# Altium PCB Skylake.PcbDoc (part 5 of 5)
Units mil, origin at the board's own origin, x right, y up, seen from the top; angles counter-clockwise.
Board outline 4000 x 4000 mil, 8 copper layers (TOP LAYER, GND1#2, SIG1#3, SIG2#4, GND2#5, SIG3#6, GND3#7, BOTTOM LAYER), stack 132.6 mil thick; 343 components, 142 nets, 972 pads, 752 vias.
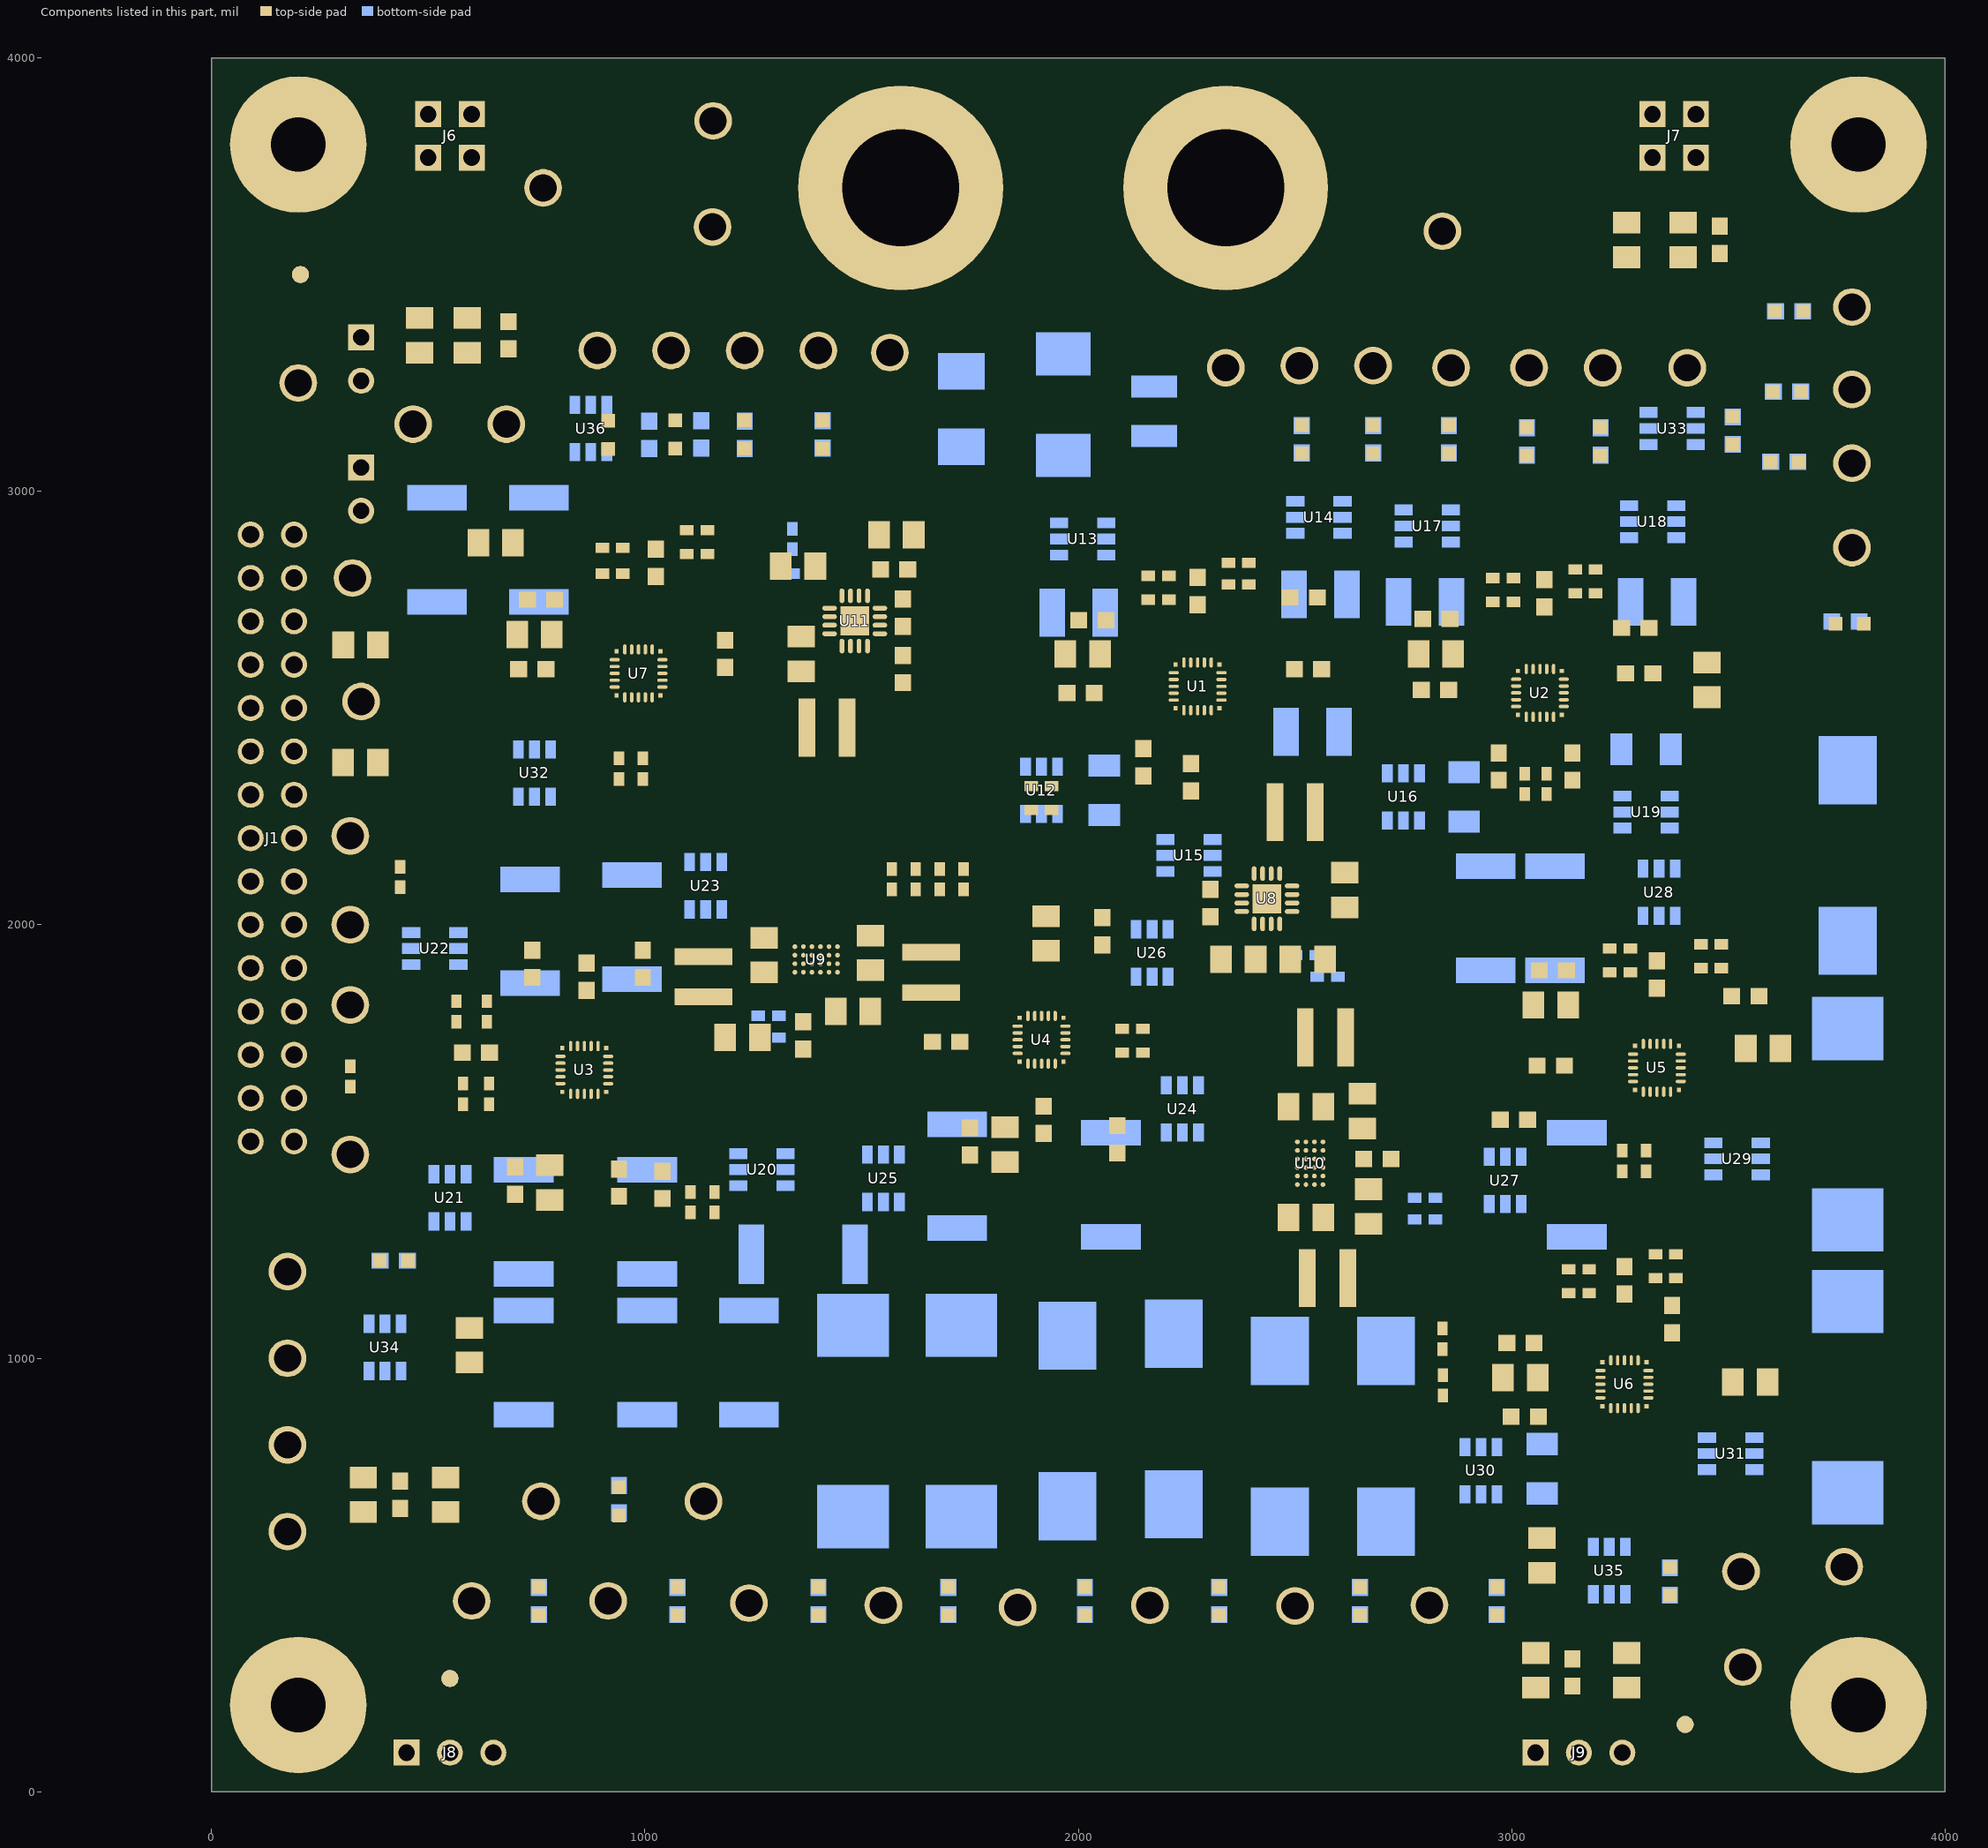
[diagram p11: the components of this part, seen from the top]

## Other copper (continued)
SIG1#3:
  pour cut-out: 1327,2559 1393,2559 1393,2522.38 1353.39,2522.38 1353.39,2522.32 1327,2522.32
  pour cut-out: 2637,1416 2703,1416 2703,1284 2637,1284
  pour cut-out: 2622,1636 2688,1636 2688,1504 2622,1504
  pour cut-out: 1159,1707 1159,1773 1291,1773 1291,1707
  pour cut-out: 1414,1767 1414,1833 1546,1833 1546,1767
  pour cut-out: 2582,2146 2648,2146 2648,2014 2582,2014
  pour cut-out: 1327,2691 1393,2691 1393,2559 1327,2559
  pour cut-out: 2566.22,2192.59 2526.14,2192.59 2526.14,2327.77 2566.22,2327.77 2566.22,2192.56
  pour cut-out: 2636.22,1672.11 2596.16,1672.11 2596.16,1807.29 2636.24,1807.29 2636.24,1672.08
  pour cut-out: 2641.09,1117.1 2601.01,1117.1 2601.01,1252.28 2641.09,1252.28 2641.09,1117.07
  pour cut-out: 1592.42,1823.22 1592.42,1863.28 1727.6,1863.28 1727.6,1823.2 1592.39,1823.2
  pour cut-out: 1067.57,1813.05 1067.57,1853.11 1202.75,1853.11 1202.75,1813.03 1067.54,1813.03
  pour cut-out: 1337.71,1925.55 1337.71,1937.71 1392.31,1937.71 1392.31,1921.82 1337.67,1921.82 1337.67,1925.52
  pour cut-out: 1397.43,1925.53 1397.43,1937.69 1451.84,1937.69 1451.84,1921.8 1397.39,1921.8 1397.39,1925.5
  pour cut-out: 2520.69,1506.47 2532.85,1506.47 2532.85,1454.35 2516.96,1454.35 2516.96,1506.51 2520.66,1506.51
  pour cut-out: 1067.1,1906.59 1067.1,1946.66 1202.28,1946.66 1202.28,1906.57 1067.07,1906.57
  pour cut-out: 1591.95,1916.26 1591.95,1956.33 1727.14,1956.33 1727.14,1916.25 1591.93,1916.25
  pour cut-out: 2520.69,1447.41 2532.85,1447.41 2532.85,1395.29 2516.96,1395.29 2516.96,1447.45 2520.66,1447.45
  pour cut-out: 2508.03,1252.14 2548.1,1252.14 2548.1,1116.97 2508.02,1116.97 2508.02,1252.18
  pour cut-out: 2503.24,1807.44 2543.31,1807.44 2543.31,1672.26 2503.23,1672.26 2503.23,1807.47
  pour cut-out: 2425.18,2133.53 2470.5,2133.53 2470.5,2101.29 2419.57,2101.29 2419.57,2133.42 2425.18,2133.42
  pour cut-out: 2433.41,2327.8 2473.49,2327.8 2473.49,2192.62 2433.41,2192.62 2433.41,2327.83
  pour cut-out: 1472.71,2657.64 1498.66,2657.64 1498.66,2633.94 1469.22,2633.94 1469.22,2657.71 1472.75,2657.71
  pour cut-out: 1353.32,2522.76 1393.39,2522.76 1393.39,2387.58 1353.31,2387.58 1353.31,2522.79
  pour cut-out: 1446.23,2522.57 1486.3,2522.57 1486.3,2387.39 1446.22,2387.39 1446.22,2522.6
  pour cut-out: 2840,3545 cw(c2840,3600) 2785,3600 cw(c2840,3600) 2840,3655 cw(c2840,3600) 2895,3600 cw(c2840,3600)
  text ".Layer_Name" at 591.64,-858.77 h60
SIG2#4:
  pour cut-out: 1327,2559 1393,2559 1393,2522.38 1353.39,2522.38 1353.39,2522.32 1327,2522.32
  pour cut-out: 2637,1416 2703,1416 2703,1284 2637,1284
  pour cut-out: 2622,1636 2688,1636 2688,1504 2622,1504
  pour cut-out: 2582,2146 2648,2146 2648,2014 2582,2014
  pour cut-out: 1159,1707 1159,1773 1291,1773 1291,1707
  pour cut-out: 1414,1767 1414,1833 1546,1833 1546,1767
  pour cut-out: 1327,2691 1393,2691 1393,2559 1327,2559
  pour cut-out: 1393.33,2387.42 1353.26,2387.42 1353.26,2522.6 1393.34,2522.6 1393.34,2387.39
  pour cut-out: 2566.33,2192.42 2526.26,2192.42 2526.26,2327.6 2566.34,2327.6 2566.34,2192.39
  pour cut-out: 2641.33,1117.42 2601.26,1117.42 2601.26,1252.6 2641.34,1252.6 2641.34,1117.39
  pour cut-out: 2636.33,1672.42 2596.26,1672.42 2596.26,1807.6 2636.34,1807.6 2636.34,1672.39
  pour cut-out: 1592.42,1823.67 1592.42,1863.74 1727.6,1863.74 1727.6,1823.66 1592.39,1823.66
  pour cut-out: 1067.42,1813.66 1067.42,1853.74 1202.6,1853.74 1202.6,1813.66 1067.39,1813.66
  pour cut-out: 1392.48,1934.02 1392.48,1921.86 1338.06,1921.86 1338.06,1937.75 1392.52,1937.75 1392.52,1934.05
  pour cut-out: 1451.82,1934.07 1451.82,1921.91 1397.4,1921.91 1397.4,1937.8 1451.86,1937.8 1451.86,1934.1
  pour cut-out: 2528.99,1392.34 2516.83,1392.34 2516.83,1446.76 2532.72,1446.76 2532.72,1392.3 2529.02,1392.3
  pour cut-out: 2529.27,1452.38 2517.11,1452.38 2517.11,1506.8 2533,1506.8 2533,1452.34 2529.3,1452.34
  pour cut-out: 1067.42,1906.66 1067.42,1946.74 1202.6,1946.74 1202.6,1906.66 1067.39,1906.66
  pour cut-out: 1592.44,1916.6 1592.44,1956.67 1727.62,1956.67 1727.62,1916.59 1592.41,1916.59
  pour cut-out: 2508.31,1253.26 2548.38,1253.26 2548.38,1118.07 2508.3,1118.07 2508.3,1253.28
  pour cut-out: 2503.41,1807.58 2543.47,1807.58 2543.47,1672.4 2503.39,1672.4 2503.39,1807.61
  pour cut-out: 2406.01,2117.53 2405.47,2118.07 2405.47,2330.3 2415.08,2339.91 2472.69,2339.91 2486.36,2326.24 2486.36,2107.36 2476.25,2097.25 2418.1,2097.25 2406.01,2109.34
  pour cut-out: 1456.7,2652.79 1456.7,2609.13 1429.59,2582.02 1429.59,2388.54 1443.84,2374.29 1444.76,2375.21 1491.17,2375.21 1503.58,2387.62 1503.58,2654.64 1496.88,2661.34 1464.98,2661.34 1457,2653.36
  text ".Layer_Name" at 595.57,-859.7 h60
GND2#5:
  pour cut-out: 1327,2559 1393,2559 1393,2522.38 1353.39,2522.38 1353.39,2522.32 1327,2522.32
  pour cut-out: 941,2718 850,2627 850,2529 939,2440 1129,2440 1188,2499 1188,2553 1209,2574 1209,3012 1187,3034 1187,3127 1219,3159 1750,3159 1766,3175 1954,3175 2245,2884 2329,2884 2404,2809 2404,2700 2368,2664 2269,2664 2256,2677 2248,2669 2265,2652 2376,2652 2417,2693 2417,2815 2334,2898 2250,2898 1960,3188 1758,3188 1743,3173 1209,3173 1173,3137 1173,3029 1197,3005 1197,2582 1175,2560 1175,2505 1123,2453 943,2453 860,2536 860,2620 944,2704 945,2704 945,2718
  pour cut-out: 3082.93,2682.21 3076.13,2689 2983,2689 2961,2667 2895,2667 2876,2648 2876,2462 2906,2432 2960,2432 3078,2314 3078,2171 3360,1889 3397,1889 3428,1858 3428,1811 3412.12,1795.12 3376.77,1795.12 3376.77,1804.88 3376.9,1805 3407,1805 3418,1816 3418,1852 3392,1878 3355,1878 3067,2166 3067,2310 2955,2422 2900,2422 2865,2457 2865,2652 2891,2678 2957,2678 2978,2699 3079.93,2699 3089.82,2689.1
  pour cut-out: 991,2726 940,2726 844,2630 844,2526 967,2403 1156,2403 1202,2449 1202,2547 1245,2590 1245,2701 1217,2729 1217,3018 1196,3039 1196,3110 1233,3147 1754,3147 1776,3169 1950,3169 2245,2874 2319,2874 2366,2827 2366,2701 2339,2674 2315,2674 2315,2685 2335,2685 2355,2705 2355,2822 2314,2863 2241,2863 1947,3157 1779,3157 1759,3137 1240,3137 1208,3105 1208,3043 1226,3025 1226,2734 1254,2706 1254,2586 1211,2543 1211,2444 1160,2393 964,2393 835,2522 835,2635 936,2736 996,2736 1012,2720 1005,2713 1004,2713
  pour cut-out: 1159,1707 1159,1773 1291,1773 1291,1707
  pour cut-out: 1414,1767 1414,1833 1546,1833 1546,1767
  pour cut-out: 2637,1416 2703,1416 2703,1284 2637,1284
  pour cut-out: 2622,1636 2688,1636 2688,1504 2622,1504
  pour cut-out: 2582,2146 2648,2146 2648,2014 2582,2014
  pour cut-out: 1327,2691 1393,2691 1393,2559 1327,2559
  pour cut-out: 1392.93,2387.35 1352.86,2387.35 1352.86,2522.53 1392.94,2522.53 1392.94,2387.32
  pour cut-out: 2640.93,1117.35 2600.86,1117.35 2600.86,1252.53 2640.94,1252.53 2640.94,1117.32
  pour cut-out: 2635.93,1672.35 2595.86,1672.35 2595.86,1807.53 2635.94,1807.53 2635.94,1672.32
  pour cut-out: 2565.93,2192.35 2525.86,2192.35 2525.86,2327.53 2565.94,2327.53 2565.94,2192.32
  pour cut-out: 1592.35,1824.07 1592.35,1864.14 1727.53,1864.14 1727.53,1824.06 1592.32,1824.06
  pour cut-out: 1067.35,1814.07 1067.35,1854.14 1202.53,1854.14 1202.53,1814.06 1067.32,1814.06
  pour cut-out: 1392.48,1933.86 1392.48,1921.7 1338.07,1921.7 1338.07,1937.59 1392.52,1937.59 1392.52,1933.89
  pour cut-out: 1451.69,1934.26 1451.69,1922.1 1397.28,1922.1 1397.28,1937.99 1451.73,1937.99 1451.73,1934.29
  pour cut-out: 2529.28,1393.12 2517.12,1393.12 2517.12,1447.53 2533.01,1447.53 2533.01,1393.08 2529.31,1393.08
  pour cut-out: 2529.22,1452.34 2517.06,1452.34 2517.06,1506.75 2532.95,1506.75 2532.95,1452.3 2529.25,1452.3
  pour cut-out: 1592.38,1916.61 1592.38,1956.68 1727.56,1956.68 1727.56,1916.59 1592.35,1916.59
  pour cut-out: 1067.35,1907.07 1067.35,1947.14 1202.53,1947.14 1202.53,1907.06 1067.32,1907.06
  pour cut-out: 2508.38,1252.82 2548.45,1252.82 2548.45,1117.64 2508.37,1117.64 2508.37,1252.86
  pour cut-out: 2503.28,1807.55 2543.35,1807.55 2543.35,1672.36 2503.27,1672.36 2503.27,1807.57
  pour cut-out: 2407.76,2119.98 2407.22,2120.53 2407.22,2332.75 2416.83,2342.36 2474.44,2342.36 2488.11,2328.69 2488.11,2109.81 2478,2099.7 2419.85,2099.7 2407.76,2111.79
  pour cut-out: 1457.04,2652.76 1457.04,2609.1 1429.93,2581.99 1429.93,2388.51 1444.18,2374.26 1445.1,2375.18 1491.51,2375.18 1503.92,2387.59 1503.92,2654.61 1497.22,2661.31 1465.32,2661.31 1457.34,2653.33
  pour cut-out: 3365,1787.5 cw(c3365,1800) 3352.5,1800 cw(c3365,1800) 3365,1812.5 cw(c3365,1800) 3377.5,1800 cw(c3365,1800)
  pour cut-out: 3094.7,2664.83 cw(c3094.7,2677.33) 3082.2,2677.33 cw(c3094.7,2677.33) 3094.7,2689.83 cw(c3094.7,2677.33) 3107.2,2677.33 cw(c3094.7,2677.33)
  pour cut-out: 2305,2667.5 cw(c2305,2680) 2292.5,2680 cw(c2305,2680) 2305,2692.5 cw(c2305,2680) 2317.5,2680 cw(c2305,2680)
  pour cut-out: 1015,2697.5 cw(c1015,2710) 1002.5,2710 cw(c1015,2710) 1015,2722.5 cw(c1015,2710) 1027.5,2710 cw(c1015,2710)
  pour cut-out: 1015,2700 cw(c1015,2710) 1005,2710 cw(c1015,2710) 1015,2720 cw(c1015,2710) 1025,2710 cw(c1015,2710)
  pour cut-out: 1015,2700 cw(c1015,2710) 1005,2710 cw(c1015,2710) 1015,2720 cw(c1015,2710) 1025,2710 cw(c1015,2710)
  pour cut-out: 1015,2700 cw(c1015,2710) 1005,2710 cw(c1015,2710) 1015,2720 cw(c1015,2710) 1025,2710 cw(c1015,2710)
  text ".Layer_Name" at 586.85,-860.23 h60
SIG3#6:
  pour cut-out: 1327.69,2558.33 1393.69,2558.33 1393.69,2521.71 1354.08,2521.71 1354.08,2521.65 1327.69,2521.65
  pour cut-out: 1159,1707 1159,1773 1291,1773 1291,1707
  pour cut-out: 1414,1767 1414,1833 1546,1833 1546,1767
  pour cut-out: 2637,1416 2703,1416 2703,1284 2637,1284
  pour cut-out: 2622,1636 2688,1636 2688,1504 2622,1504
  pour cut-out: 2582,2146 2648,2146 2648,2014 2582,2014
  pour cut-out: 1327,2691 1393,2691 1393,2559 1327,2559
  pour cut-out: 1392.93,2387.47 1352.86,2387.47 1352.86,2522.65 1392.94,2522.65 1392.94,2387.44
  pour cut-out: 2640.93,1117.47 2600.86,1117.47 2600.86,1252.65 2640.94,1252.65 2640.94,1117.44
  pour cut-out: 2635.93,1672.47 2595.86,1672.47 2595.86,1807.65 2635.94,1807.65 2635.94,1672.44
  pour cut-out: 2565.93,2192.47 2525.86,2192.47 2525.86,2327.65 2565.94,2327.65 2565.94,2192.44
  pour cut-out: 1592.47,1824.07 1592.47,1864.14 1727.65,1864.14 1727.65,1824.06 1592.44,1824.06
  pour cut-out: 1067.47,1814.07 1067.47,1854.14 1202.65,1854.14 1202.65,1814.05 1067.44,1814.05
  pour cut-out: 1392.71,1934.26 1392.71,1922.1 1338.3,1922.1 1338.3,1937.99 1392.75,1937.99 1392.75,1934.29
  pour cut-out: 1451.76,1934.21 1451.76,1922.05 1397.35,1922.05 1397.35,1937.94 1451.8,1937.94 1451.8,1934.24
  pour cut-out: 2529.11,1393.1 2516.95,1393.1 2516.95,1447.51 2532.84,1447.51 2532.84,1393.06 2529.14,1393.06
  pour cut-out: 2529.2,1452.24 2517.04,1452.24 2517.04,1506.65 2532.93,1506.65 2532.93,1452.2 2529.23,1452.2
  pour cut-out: 1067.47,1907.07 1067.47,1947.14 1202.65,1947.14 1202.65,1907.05 1067.44,1907.05
  pour cut-out: 1592.19,1916.52 1592.19,1956.59 1727.37,1956.59 1727.37,1916.51 1592.16,1916.51
  pour cut-out: 2508.28,1252.69 2548.34,1252.69 2548.34,1117.51 2508.26,1117.51 2508.26,1252.72
  pour cut-out: 2503.14,1807.13 2543.21,1807.13 2543.21,1671.95 2503.13,1671.95 2503.13,1807.16
  pour cut-out: 2405.93,2118.28 2405.39,2118.82 2405.39,2331.05 2415,2340.66 2472.61,2340.66 2486.28,2326.99 2486.28,2108.11 2476.17,2098 2418.02,2098 2405.93,2110.09
  pour cut-out: 1457.81,2652.43 1457.81,2608.77 1430.7,2581.66 1430.7,2388.18 1444.95,2373.93 1445.87,2374.85 1492.28,2374.85 1504.69,2387.26 1504.69,2654.28 1497.99,2660.98 1466.09,2660.98 1458.11,2653
  text ".Layer_Name" at 585.44,-857.07 h60
GND3#7:
  pour cut-out: 1327,2559 1393,2559 1393,2522.38 1353.39,2522.38 1353.39,2522.32 1327,2522.32
  pour cut-out: 2258,2682 2247,2693 2267,2713 2267,2899 2223,2943 2223,3311 2299,3387 2909,3387 2980,3316 2980,3041 3148,2873 3148,2669 3123,2644 3048,2644 3038,2654 3015,2654 3005,2644 3005,2615 3016,2604 3016,2541 2971,2496 2971,2402 3036,2337 3216,2337 3259,2294 3259,1879 3319,1819 3319,1792 3311,1784 3300,1784 3291,1793 3232,1793 3163,1724 3163,1395 3192,1366 3192,1117 3227,1082 3218,1073 3178,1113 3178,1360 3149,1389 3149,1732 3223,1806 3293,1806 3298,1811 3298,1817 3246,1869 3246,2286 3209,2323 3028,2323 2957,2394 2957,2503 3002,2548 3002,2597 2992,2607 2992,2655 3014,2677 3038,2677 3058,2657 3115,2657 3135,2677 3135,2868 2963,3040 2963,3312 2904,3371 2308,3371 2238,3301 2238,2947 2280,2905 2280,2704
  pour cut-out: 364,1824 508,1824 613,1719 657,1719 726,1650 736,1650 765,1679 765,1756 821,1812 976,1812 1251,1537 1592,1537 1768,1713 1775,1713 1775,1694 1598,1517 1252,1517 970,1799 828,1799 778,1749 778,1662 739,1623 725,1623 715,1633 715,1639 650,1704 609,1704 507,1806 364,1806
  pour cut-out: 81,1969 98,1969 98,1928 138,1888 256,1888 293,1851 282,1840 250,1872 131,1872 81,1922
  pour cut-out: 114.5,2035.5 125,2025 143,2043 244,2043 276,2075 737,2075 912,2250 912,2323 999,2410 999,2533 990,2542 990,2683 966,2707 957,2698 977,2678 977,2535 985,2527 985,2418 897,2330 897,2258 730,2091 268,2091 235,2058 137,2058
  pour cut-out: 3278,1072 3255,1095 3255,1323 3174,1404 3174,1720 3213,1759 3314,1759 3353,1798 3363,1788 3321,1746 3218,1746 3186,1714 3186,1409 3267,1328 3267,1101 3287,1081
  pour cut-out: 2307,2692 2338,2723 2338,2892 2250,2980 2250,3303 2308,3361 2902,3361 2956,3307 2956,3026 3080,2902 3080,2701 3092,2689 3083,2680 3066,2697 3066,2894 2939,3021 2939,3298 2892,3345 2317,3345 2265,3293 2265,2985 2350,2900 2350,2715 2317,2682
  pour cut-out: 346,2038 363,2055 902,2055 1007,2160 1007,2479 1032,2504 1031,2505 1031,2601 998,2634 998,2703 1002,2707 1011,2698 1011,2639 1046,2604 1046,2495 1023,2472 1023,2154 909,2040 374,2040 359,2025
  pour cut-out: 220,2008 276,2008 276,1993 220,1993
  pour cut-out: 727,1705 735,1705 735,1747 814,1826 977,1826 1188,1615 1381,1615 1406,1640 1636,1640 1727,1731 1760,1731 1782,1753 1773,1762 1754,1743 1720,1743 1630,1653 1396,1653 1374,1631 1199,1631 991,1839 811,1839 725,1753 725,1707
  pour cut-out: 312,1957 312,1924 384,1852 562,1852 718,1696 727,1705 567,1865 392,1865 327,1930 327,1957
  pour cut-out: 1159,1707 1159,1773 1291,1773 1291,1707
  pour cut-out: 1414,1767 1414,1833 1546,1833 1546,1767
  pour cut-out: 2637,1416 2703,1416 2703,1284 2637,1284
  pour cut-out: 2622,1636 2688,1636 2688,1504 2622,1504
  pour cut-out: 2582,2146 2648,2146 2648,2014 2582,2014
  pour cut-out: 1327,2691 1393,2691 1393,2559 1327,2559
  pour cut-out: 1393.7,2387.96 1353.63,2387.96 1353.63,2523.14 1393.71,2523.14 1393.71,2387.93
  pour cut-out: 2641.7,1117.96 2601.63,1117.96 2601.63,1253.14 2641.71,1253.14 2641.71,1117.93
  pour cut-out: 2636.7,1672.96 2596.63,1672.96 2596.63,1808.14 2636.71,1808.14 2636.71,1672.93
  pour cut-out: 2566.7,2192.96 2526.63,2192.96 2526.63,2328.14 2566.71,2328.14 2566.71,2192.93
  pour cut-out: 1592.96,1823.3 1592.96,1863.37 1728.14,1863.37 1728.14,1823.29 1592.93,1823.29
  pour cut-out: 1067.96,1813.3 1067.96,1853.36 1203.14,1853.36 1203.14,1813.28 1067.93,1813.28
  pour cut-out: 1392.6,1934.09 1392.6,1921.93 1338.19,1921.93 1338.19,1937.82 1392.64,1937.82 1392.64,1934.12
  pour cut-out: 1451.86,1934.22 1451.86,1922.06 1397.45,1922.06 1397.45,1937.95 1451.9,1937.95 1451.9,1934.25
  pour cut-out: 2529,1393.06 2516.84,1393.06 2516.84,1447.47 2532.73,1447.47 2532.73,1393.02 2529.03,1393.02
  pour cut-out: 2529.18,1452.2 2517.02,1452.2 2517.02,1506.61 2532.91,1506.61 2532.91,1452.16 2529.21,1452.16
  pour cut-out: 1592.24,1916.44 1592.24,1956.51 1727.41,1956.51 1727.41,1916.43 1592.2,1916.43
  pour cut-out: 1067.96,1906.3 1067.96,1946.36 1203.14,1946.36 1203.14,1906.28 1067.93,1906.28
  pour cut-out: 2508.45,1253.3 2548.53,1253.3 2548.53,1118.12 2508.45,1118.12 2508.45,1253.33
  pour cut-out: 2503.21,1808.09 2543.28,1808.09 2543.28,1672.91 2503.2,1672.91 2503.2,1808.12
  pour cut-out: 2406.33,2118.94 2405.79,2119.48 2405.79,2331.71 2415.4,2341.32 2473.01,2341.32 2486.68,2327.65 2486.68,2108.77 2476.57,2098.66 2418.42,2098.66 2406.33,2110.75
  pour cut-out: 1459.12,2652.43 1459.12,2608.77 1432.01,2581.66 1432.01,2388.18 1446.26,2373.93 1447.18,2374.85 1493.59,2374.85 1506,2387.26 1506,2654.28 1499.3,2660.98 1467.4,2660.98 1459.42,2653
  pour cut-out: 190,1960 cw(c190,2000) 150,2000 cw(c190,2000) 190,2040 cw(c190,2000) 230,2000 cw(c190,2000)
  pour cut-out: 320,1948 cw(c320,2000) 268,2000 cw(c320,2000) 320,2052 cw(c320,2000) 372,2000 cw(c320,2000)
  pour cut-out: 3365,1787.5 cw(c3365,1800) 3352.5,1800 cw(c3365,1800) 3365,1812.5 cw(c3365,1800) 3377.5,1800 cw(c3365,1800)
  pour cut-out: 3290,1057.5 cw(c3290,1070) 3277.5,1070 cw(c3290,1070) 3290,1082.5 cw(c3290,1070) 3302.5,1070 cw(c3290,1070)
  pour cut-out: 3094.7,2664.83 cw(c3094.7,2677.33) 3082.2,2677.33 cw(c3094.7,2677.33) 3094.7,2689.83 cw(c3094.7,2677.33) 3107.2,2677.33 cw(c3094.7,2677.33)
  pour cut-out: 2305,2667.5 cw(c2305,2680) 2292.5,2680 cw(c2305,2680) 2305,2692.5 cw(c2305,2680) 2317.5,2680 cw(c2305,2680)
  pour cut-out: 1785,1752.18 cw(c1785,1764.68) 1772.5,1764.68 cw(c1785,1764.68) 1785,1777.18 cw(c1785,1764.68) 1797.5,1764.68 cw(c1785,1764.68)
  pour cut-out: 1015,2697.5 cw(c1015,2710) 1002.5,2710 cw(c1015,2710) 1015,2722.5 cw(c1015,2710) 1027.5,2710 cw(c1015,2710)
  pour cut-out: 730,1682.5 cw(c730,1695) 717.5,1695 cw(c730,1695) 730,1707.5 cw(c730,1695) 742.5,1695 cw(c730,1695)
  text ".Layer_Name" at 586.85,-860.23 h60
BOTTOM LAYER:
  rectangle net GND: 2240,2515 2310,2585
  rectangle net GND: 3030,2500 3100,2570
  rectangle net GND: 2401.39,2026.35 2468.64,2093.41
  rectangle net GND: 1450.39,2667.35 1517.64,2734.41
  pour cut-out: 1216.37,2551.97 1282.37,2551.97 1282.37,2515.35 1242.76,2515.35 1242.76,2515.29 1216.37,2515.29
  region net V3.3DX_3G4G: 2070.84,1971.74 2101.6,1971.74 2109.86,1963.48 2109.86,1912.39 2119.13,1903.12 2143.39,1903.12 2145.04,1901.47 2145.04,1858.39 2139.39,1852.74 2093.24,1852.74 2064.06,1881.92 2064.06,1964.96
  region net GND: 3700,2480 3850,2480 3880,2450 3880,2285 3855,2260 3700,2260 3660.83,2299.17 3660.83,2440.83
  region net NetR85_2: 3840,2080 3875,2045 3875,1685 3855,1665 3700,1665 3670,1695 3670,2040 3710,2080
  pour cut-out: 1451.48,1934.02 1451.48,1921.86 1397.07,1921.86 1397.07,1937.75 1451.52,1937.75 1451.52,1934.05
  pour cut-out: 1392.58,1934.18 1392.58,1922.02 1338.17,1922.02 1338.17,1937.91 1392.62,1937.91 1392.62,1934.21
  pour cut-out: 2529.04,1452.29 2516.88,1452.29 2516.88,1506.7 2532.77,1506.7 2532.77,1452.25 2529.07,1452.25
  pour cut-out: 2529.17,1392.58 2517.01,1392.58 2517.01,1446.99 2532.9,1446.99 2532.9,1392.54 2529.2,1392.54
  region net V3.3DX_WIFI: 3864,841 3695,841 3695,617 3864,617
  region net GND: 2556.45,2835.07 2560.66,2839.28 2639.58,2839.28 2651.08,2827.78 2651.08,2703.66 2643.03,2695.61 2565.64,2695.61 2551.85,2709.4 2551.85,2831.62 2555.68,2835.45
  region net GND: 2680.69,2808.39 2800.38,2808.39 2811.75,2797.02 2811.75,2534.17 2777.52,2499.94 2725.75,2499.94 2672.68,2553.01 2672.68,2800.38
  region net NetR72_2: 1177.26,1315.37 1295.59,1315.37 1314.17,1296.79 1314.17,1069.26 1293.95,1049.04 1172.61,1049.04 1153.39,1068.26 1153.39,1291.5
  region net V1(1.8V): 3453.44,3125.74 3459.57,3119.61 3459.57,3074.75 3451.51,3066.69 3404.37,3066.69 3397.93,3073.13 3397.93,3121.22 3402.45,3125.74
  region net V3(3.3V): 3142.8,480.99 3195.63,480.99 3200.42,476.2 3200.42,406.22 3193.19,398.99 3142.99,398.99 3135.28,406.7 3135.28,473.47
  region net V2(3.3V): 432.45,1148.25 474.67,1148.25 481.32,1141.6 481.32,1062.38 475.97,1057.03 426.84,1057.03 424.53,1059.34 424.53,1140.33
  region net V3.3DX_USBSDIO: 938.81,1503.46 1087.54,1503.46 1103.27,1487.73 1103.27,1410.85 1090.88,1398.46 933.15,1398.46 923.12,1408.49 923.12,1487.77
  region net V3.3S: 3041.4,846.33 3122.09,846.33 3137.35,831.07 3137.35,763.95 3128.53,755.13 3041.85,755.13 3025.13,771.85 3025.13,830.06
  region net V3.3A_EC: 672.46,1913.43 804.6,1913.43 814.25,1903.78 814.25,1813.18 795.4,1794.33 676.61,1794.33 657.96,1812.98 657.96,1898.93
  region net V3.3DX_SENSORS: 921.75,1927.74 921.76,1927.75 1056.69,1927.75 1070.13,1914.31 1070.13,1852.68 1059.33,1841.88 898.97,1841.88 891.67,1849.18 891.67,1912.56 906.86,1927.75 922.34,1927.75
  region net V3.3DX_EDP: 575.42,1512 588.3,1524.88 660.49,1524.88 678.73,1506.64 678.73,1405.87 664.3,1391.44 583.63,1391.44 575.42,1399.65
  text ".Layer_Name" at 577,-858.49 h60
Multi-Layer:
  circle w8: c-264,1 r26
  circle w8: c-264,1 r13
  circle w8: c-264,1 r40
  circle w8: c4324,-2 r26
  circle w8: c4324,-2 r13
  circle w8: c4324,-2 r40
  circle w8: c4326,4009 r26
  circle w8: c4326,4009 r13
  circle w8: c4326,4009 r40
  lines w8: -320,0 -264,0 ; -264,-56 -264,0 ; -264,56 -264,0 ; -208,0 -264,0 ; 4268,-3 4324,-3 ; 4270,4008 4326,4008 ; 4324,-59 4324,-3 ; 4324,53 4324,-3 ; 4326,3952 4326,4008 ; 4326,4064 4326,4008 ; 4380,-3 4324,-3 ; 4382,4008 4326,4008

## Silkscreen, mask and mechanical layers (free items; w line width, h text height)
Top Overlay:
  drawing of 296 lines, arcs and shapes, not listed
  text "1" at 3475,3010 h30
  text "V1(1.8V)" at 3398,2995.88 h30 r90
  text "J1" at 130,2952 h30
  text "GPIO12" at 28.26,2837.09 h30
  text "GND" at 61.3,2742.6 h30
  text "NETJ1_6" at 140.4,2742.6 h30
  text "GND" at 53.22,2639.09 h30
  text "TPS22993" at 870.47,2556.79 h30 r90
  text "TPS62130" at 1421,2553 h30
  text "GND" at 58.36,2535.5 h30
  text "2" at 3790,2530 h30
  text "TPS22993" at 2136.98,2512.86 h30 r90
  text "TPS22993" at 2933.06,2436.68 h30 r90
  text "GPIO6" at 17.13,2336.86 h30
  text "GPIO7" at 147.4,2337.32 h30
  text "GPIO4" at 16.67,2236.15 h30
  text "GPIO5" at 140.93,2236.15 h30
  text "1" at 3877.76,2143.35 h30
  text "GND" at 55.6,2140.8 h30
  text "NETJ2_6" at 139.8,2138.2 h30
  text "TPS62151" at 2186.55,2122.86 h30
  text "GPIO2" at 21.32,2038.15 h30
  text "GPIO3" at 145.47,2037.86 h30
  text "TPS62182" at 1421,1995 h30 r90
  text "SDA" at 66,1941.9 h30
  text "SCL" at 167.9,1940.8 h30
  text "TPS22993" at 1860.28,1856.14 h30
  text "TPS22993" at 827.52,1781.3 h30
  text "GPIO8" at 18.6,1636.83 h30
  text "GPIO9" at 155.81,1637.35 h30
  text "TPS22993" at 3202.13,1623.85 h30 r90
  text "GND" at 52.62,1537.66 h30
  text "GND" at 151.93,1538.18 h30
  text "2" at 3875,1510 h30
  text "GPIO10" at 25,1440 h30
  text "GPIO11" at 140,1440 h30
  text "TPS62182" at 2295.61,1406.94 h30
  text "V3.3A_EC" at 330.21,1153.12 h30
  text "TI Design" at 711.66,1127.85 h50
  text "Power Regulation & Distribution for Intel SkyLake" at 769.84,1047.85 h50
  text "[TPS62151 + TPS62182 (x2) + TPS62310 + TPS22993 (x7)]" at 769.84,973.67 h50
  text "TPS22993" at 3141.9,915.98 h30 r90
  text "Solution Size: 54.356mmx 80.137mm (4355.926mm^2)" at 773.62,902.83 h50
  text "V2(3.3V)" at 894.16,614.99 h30 r90
  text "V3.3S" at 2640.25,527.79 h30 r90
  text "V3.3M" at 2316.13,525.73 h30 r90
  text "V3(3.3V)" at 3441.75,424.71 h30 r90
  text "V3.3Dx_3G4G" at 2079,349.19 h30 r90
  text "V3.3Dx_EDP" at 821.49,336.24 h30 r90
  text "V3.3Dx_SSD" at 2914.44,323.51 h30 r90
  text "V3.3Dx_AUDIO" at 1765.76,314.6 h30 r90
  text "V3.3Dx_USBSDIO" at 1463.26,280.29 h30 r90
  text "V3.3Dx_SENSORS" at 1147.65,275.92 h30 r90
  text ".PRJ_Number" at 1061.05,172.31 h60
  text ".PCB_Rev" at 1355.83,83.21 h60
  text ".Layer_Name" at 577,-858.49 h60
Bottom Overlay:
  text ".Layer_Name" at 577,-858.49 h60
Top Paste:
  region: 2240,2585 2310,2585 2310,2515 2240,2515
  region: 3030,2570 3100,2570 3100,2500 3030,2500
  text ".Layer_Name" at 577,-858.49 h60
Bottom Paste:
  text ".Layer_Name" at 577,-858.49 h60
Top Solder:
  region: 3028,2572 3028,2498 3102,2498 3102,2572
  region: 2238,2587 2312,2587 2312,2513 2238,2513
  text ".Layer_Name" at 577,-858.49 h60
  text ".Layer_Name" at 577,-858.49 h60
Bottom Solder:
  drawing of 32 lines, arcs and shapes, not listed
  text ".Layer_Name" at 577,-858.49 h60
Drill Guide:
  text ".Layer_Name" at 577,-858.49 h60
M1 Board Outline:
  the board outline again, w10
  text ".Layer_Name" at 577,-858.49 h60
M2 Board Dimensions:
  rectangle: 124.5,-410.5 499.5,-285.5
  rectangle: -0.5,-285.5 124.5,-160.5
  lines w7: -0.5,-285.5 999.5,-285.5 ; 124.5,-410.5 124.5,-160.5 ; 249.5,-410.5 249.5,-160.5 ; 499.5,-410.5 499.5,-160.5 ; 749.5,-410.5 749.5,-160.5 ; -0.5,-410.5 -0.5,-160.5 999.5,-160.5 999.5,-410.5 -0.5,-410.5
  lines w10: -0.5,-475.5 -0.5,-455.5 ; 59.5,-485.5 -0.5,-465.5 ; 59.5,-445.5 -0.5,-465.5 ; 223.58,-465.5 -0.5,-465.5 ; 775.42,-465.5 999.5,-465.5 ; 939.5,-485.5 999.5,-465.5 ; 939.5,-445.5 999.5,-465.5 ; 999.5,-475.5 999.5,-455.5
  text "1000 (mil)" at 233.58,-501.49 h60
  text ".Layer_Name" at 577,-858.49 h60
M3 3D STEP Top:
  text ".Layer_Name" at 577,-858.49 h60
M4 3D STEP Bottom:
  text ".Layer_Name" at 577,-858.49 h60
M5 Assembly Top:
  lines w10: -292,-930.17 6308,-930.17 ; -292,-726.83 6310,-726.83 ; -292,-523.5 -292,-1133.5 3713,-1133.5 6310,-1133.5 6310,-523.5 -291.5,-523.5 -291.5,-1133.5 1284,-1133.5 ; 2173,-1133.5 2173,-523.5 ; 3440,-726.83 3440,-523.5 ; 4280,-726.83 4280,-523.5 ; 4902,-1140 4902,-937.17
  text "U9" at 1381.7,1912.71 h30
  text "U10" at 2511.22,1438.71 h30
  text "COMPONENTS MARKED 'DNP' SHOULD NOT BE POPULATED." at 1153.5,-318.5 h60
  text "ASSEMBLY VARIANT:" at 1153,-434 h60
  text ".VariantName" at 2189,-434 h60
  text "PCB VIEWED FROM TOP SIDE" at -228.5,-655.67 h60
  text "BOARD #:" at 2248,-655.67 h60
  text ".PRJ_Number" at 2793.5,-655.67 h60
  text "REV:" at 3638,-655.67 h60
  text ".PCB_Rev" at 3929.5,-655.67 h60
  text "SVN REV:" at 4476,-655.67 h60
  text ".VersionControl_RevNumber" at 4982,-655.67 h60
  text "IGNORE ->" at -228.5,-858.49 h60
  text "PLOT NAME =" at -228.5,-1064.34 h60
  text ".plot_File_Name" at 577,-1064.34 h60
  text "GENERATED    :" at 2250,-1064.34 h60
  text ".Print_Date" at 3119.5,-1064.34 h60
  text ".Print_Time" at 3848.5,-1064.34 h60
  text "TEXAS INSTRUMENTS" at 5113,-1064.34 h60
M6 Assembly Bottom:
  lines w10: -292.5,-727.33 6309.5,-727.33 ; -290.5,-930.67 6309.5,-930.67 ; 1115.5,-1140.5 1115.5,-937.67 ; 1737.5,-727.33 1737.5,-524 ; 2577.5,-727.33 2577.5,-524 ; 3844.5,-1134 3844.5,-524 ; 4733.5,-1134 6309,-1134 6309,-524 -292.5,-524 -292.5,-1134 2304.5,-1134 6309.5,-1134 6309.5,-524
  text "COMPONENTS MARKED 'DNP' SHOULD NOT BE POPULATED." at 6102,-318 h60
  text ".VariantName" at 5058,-434 h60
  text "ASSEMBLY VARIANT:" at 6097,-434 h60
  text ".VersionControl_RevNumber" at 1035.5,-656.17 h60
  text "SVN REV:" at 1541.5,-656.17 h60
  text ".PCB_Rev" at 2088,-656.17 h60
  text "REV:" at 2379.5,-656.17 h60
  text ".PRJ_Number" at 3224,-656.17 h60
  text "BOARD #:" at 3769.5,-656.17 h60
  text "PCB VIEWED FROM BOTTOM SIDE" at 6246,-656.17 h60
  text "IGNORE ->" at 2547.85,-858.49 h60
  text "TEXAS INSTRUMENTS" at 904.5,-1064.84 h60
  text ".Print_Time" at 2169,-1064.84 h60
  text ".Print_Date" at 2898,-1064.84 h60
  text "GENERATED    :" at 3767.5,-1064.84 h60
  text ".plot_File_Name" at 5440.5,-1064.84 h60
  text "PLOT NAME =" at 6246,-1064.84 h60
M9 Title Sheet:
  drawing of 57 lines, arcs and shapes, not listed
  text "1" at 739.84,8036.5 h70
  text "2" at 3235.5,8036.5 h70
  text "3" at 5724.84,8036.5 h70
  text "4" at 8231.51,8036.5 h70
  text "5" at 10730.5,8036.5 h70
  text "6" at 13235.5,8036.5 h70
  text "A" at -416.5,6893.5 h70
  text "A" at 14383.5,6893.5 h70
  text "B" at -416.5,4513.5 h70
  text "B" at 14383.5,4513.5 h70
  text "C" at -416.5,2138.5 h70
  text "C" at 14383.5,2138.5 h70
  text "PROJECT TITLE:" at 11343.5,277.5 h45
  text ".PRJ_Title" at 11393.5,144.17 h70
  text "DESIGNED FOR:" at 11343.5,-23.5 h45
  text ".PRJ_Customer" at 11393.5,-163.5 h70
  text "D" at -416.5,-231.5 h70
  text "D" at 14383.5,-231.5 h70
  text "FILE NAME:" at 11343.5,-323.5 h45
  text ".PCB_File_Name_No_Path" at 11393.5,-443.5 h70
  text "Texas Instruments (TI) and/or its licensors do not warrant the accuracy or completeness of this specification" at 6374,-605.34 h45
  text "ENGINEER:" at 11343.5,-613.5 h45
  text "LAYOUT BY:" at 12848.5,-613.5 h45
  text "or any information contained therein. TI and/or its licensors do not warrant that this design will meet" at 6329.01,-718 h45
  text ".PRJ_Engineer" at 11393.5,-768.49 h70
  text ".PCB_Layout" at 12899,-768.49 h70
  text "the specifications, will be suitable for your application or fit for any particular purpose, or will operate in" at 6329.01,-830.67 h45
  text ".Layer_Name" at 577,-858.49 h60
  text "ALTIUM DESIGNER VERSION:" at 12848.5,-923.5 h45
  text "an implementation. TI and/or its licensors do not warrant that the design is production worthy. You should" at 6329.01,-943.33 h45
  text "completely validate and test your design implementation to confirm the system functionality for your application." at 6374,-1056 h45
  text ".print_Scale" at 11393.5,-1056.83 h70
  text ".Application_BuildNumber" at 12899,-1056.83 h70
  text "1" at 739.84,-1263.5 h70
  text "2" at 3235.5,-1263.5 h70
  text "3" at 5724.84,-1263.5 h70
  text "4" at 8231.51,-1263.5 h70
  text "5" at 10730.5,-1263.5 h70
  text "6" at 13235.5,-1263.5 h70
M10 Fab Notes:
  drawing of 234 lines, arcs and shapes, not listed
  text "DESIGN INFORMATION" at 12381.02,6810 h60
  text "(REFER ALSO ARRAY/PANEL PROFILING INFORMATION)" at 12019.46,6648.29 h60
  text "BOARD SIZE" at 11333.46,6644 h60
  text "4000MIL" at 11795.78,6516.18 h60
  text "X" at 12301.46,6516.18 h60
  text "4000MIL" at 12532.78,6516.18 h60
  text "Number of Layers :" at 11736.46,6319 h60
  text "8" at 12831.27,6309 h60
  text "MIN. TRACK WIDTH:" at 11736.46,6180 h60
  text "5" at 12832.7,6180 h60
  text "MIL" at 12987.46,6180 h60
  text "MIN. CLEARANCE:" at 11736.46,6048 h60
  text "3" at 12832.7,6048 h60
  text "MIL" at 12987.46,6048 h60
  text "MIN. VIA PAD SIZE:" at 11736.46,5916 h60
  text "20" at 12802.71,5916 h60
  text "MIL" at 12987.46,5916 h60
  text "0.05mm (2MIL)" at 12431.46,5774.29 h60
  text "MINIMUM ANNULAR RING" at 11407.23,5770 h60
  text "EXTERNAL" at 13139.46,5770 h60
  text "PER" at 11607.23,5652 h60
  text "IPC-D-275 CLASS 2 LEVEL C" at 11827.23,5652 h60
  text "MIL, HOLES" at 13315.46,5539.71 h60
  text "+/-" at 12923,5539 h60
  text "+/-" at 13777,5539 h60
  text "REGISTRATION TOLERANCES:" at 11407.23,5534 h60
  text "METAL" at 12607,5534 h60
  text "5" at 13183.2,5534 h60
  text "3" at 14016.2,5534 h60
  text "MIL" at 14132.46,5534 h60
  text "MATERIAL:" at 11332.46,5324.54 h60
  text "FR-4 High Tg" at 12318.9,5184.21 h60
  text "FR-408" at 11753.46,5175.64 h60
  text "X" at 12165.46,5175.64 h60
  text "OTHER" at 13241.46,5175.64 h60
  text "62 MIL (1.6mm) +/-10%" at 12073.56,5012.92 h60
  text "THICKNESS:" at 11407.23,5008.64 h60
  text "OTHER" at 13358.46,5008.64 h60
  text "X" at 13231,5008 h60
  text "92 MIL" at 13812,5005 h60
  text "TOLERANCE:" at 11407.23,4850.64 h60
  text "X" at 12246.53,4850.64 h60
  text "ANSI IPC-6012 TYPE 3 CLASS 2" at 12433.48,4850.64 h60
  text "OTHER +/-" at 12433.46,4694.64 h60
  text "BOW & TWIST:" at 11407.23,4537.64 h60
  text "X" at 12246.53,4537.64 h60
  text "ANSI IPC-6012 TYPE 3 CLASS 2" at 12433.48,4537.64 h60
  text "OTHER +/-" at 12433.46,4379.13 h60
  text "COPPER THICKNESS (FINISHED):" at 11332.46,4243.64 h60
  text "1.4MIL (1oz)" at 12212.46,4090.92 h60
  text "2MIL (1.4oz)" at 12979.46,4090.92 h60
  text "2.8MIL (2oz)" at 13706.46,4090.92 h60
  text "OUTER:" at 11689.46,4086.64 h60
  text "X" at 13580,4085 h60
  text "1.4MIL (1oz)" at 12212.46,3933.92 h60
  text "2.8MIL (2oz)" at 12979.46,3933.92 h60
  text "N/A" at 13706,3934.29 h60
  text "INNER SIGNAL:" at 11400.38,3929.64 h60
  text "X" at 12085.42,3929.64 h60
  text "DRILLING:" at 11332.46,3790.64 h60
  text "REFERENCE:" at 11407.23,3673.64 h60
  text "X" at 12055.46,3673.64 h60
  text "AS SHOWN" at 12242.46,3673.64 h60
  text "X" at 12956.46,3673.64 h60
  text "NC_DRILL FILES" at 13093.46,3673.64 h60
  text "PTH MIN COPPER THICKNESS:" at 11407.23,3515.64 h60
  text "X" at 12757.46,3515.64 h60
  text "1MIL" at 12894.46,3515.64 h60
  text "OTHER" at 13391.46,3515.64 h60
  text "BOARD FINISH:" at 11332.46,3356.64 h60
  text "SILKSCREEN:" at 11487.68,3238.64 h60
  text "X" at 12436.46,3238.64 h60
  text "TOP" at 12562.46,3238.64 h60
  text "X" at 12946.46,3238.64 h60
  text "BOTTOM" at 13073.46,3238.64 h60
  text "SILKSCREEN COLOR:" at 11487.68,3071.64 h60
  text "X" at 12435.42,3071.64 h60
  text "WHITE" at 12562.46,3071.64 h60
  text "OTHER" at 13073.46,3071.64 h60
  text "SOLDER RESIST COLOR:" at 11487.68,2901.64 h60
  text "SEE DETAIL A" at 1342.19,2747.13 h50
  text "X" at 12055.42,2742.44 h60
  text "GREEN" at 12182.46,2742.44 h60
  text "BLUE" at 12773.46,2742.44 h60
  text "OTHER" at 13311.46,2742.44 h60
  text "SCORE OUTLINE" at 5312.61,2665.44 h60
  text "IMMERSION GOLD (ENIG)" at 12393.46,2553.92 h60
  text "ENEPIG" at 13731,2550.64 h60
  text "SURFACE FINISH:" at 11332.46,2549.64 h60
  text "X" at 12206.51,2549.64 h60
  text "IMM. TIN/SILVER OR EQUIV" at 11662,2392.64 h60
  text "OTHER" at 13093.46,2392.64 h60
  text "DETAIL A" at 5047.18,2218.87 h60
  text "ARRAY/PANEL:" at 11332.46,2213.64 h60
  text "CUT AND TRIM PER MECH LAYER 1" at 12393.46,2209.35 h60
  text "SEE DETAIL A" at 2292.12,2118.05 h50
  text "ALL 7.874MIL DRILL SHOWN IN THE MARKED AREA NEEDS TO THE SMOOTH AND NON CONDUCTIVE VIA PLUG FROM BOTTOM" at 5101,2118 h60
  text "N.C. ROUTE" at 12393.46,2057.64 h60
  text "X" at 13072.46,2057.64 h60
  text "V. SCORE" at 13259.46,2057.64 h60
  text "CERTIFICATION:" at 11332.46,1920.64 h60
  text "MATERIALS AND WORKMANSHIP FOR ALL PCBS" at 12057.46,1920.64 h60
  text "TO MEET OR EXCEED THE REQUIREMENTS OF:" at 12057.46,1822.64 h60
  text "X" at 11683.96,1686.13 h60
  text "ANSI IPC-A-600F CLASS ->" at 11822.96,1686.13 h60
  text "X" at 13462.02,1686.13 h60
  text "2" at 13580.96,1686.14 h60
  text "1" at 13265.96,1684.64 h60
  text "3" at 13934.96,1684.64 h60
  text "X" at 11686.02,1526.64 h60
  text "UL 94V-0" at 11822.96,1526.64 h60
  text "X" at 12498.02,1526.64 h60
  text "RoHS" at 12634.96,1526.64 h60
  text "OTHER" at 13279.36,1526.64 h60
  text "PER ORDER" at 13676.42,1526.64 h60
  text "ADDITIONAL REQUIREMENTS:" at 11332.46,1385.64 h60
  text "MICROSECTION:" at 11407.23,1270.64 h60
  text "YES" at 12312.96,1270.64 h60
  text "REQUIRED" at 13174.46,1114.49 h60
  text "BARE BOARD ELEC. TEST:" at 11407.23,1111.64 h60
  text "NONE" at 12712.96,1111.64 h60
  text "X" at 13047.46,1111.64 h60
  text "PER ORDER" at 13766.46,1111.64 h60
  text "MANUFACTURER'S UL:" at 11407.23,954.64 h60
  text "RAIL" at 12572.96,950.35 h60
  text "METAL" at 13064.77,950.35 h60
  text "X" at 13440,950 h60
  text "SILK" at 13576.46,950.35 h60
  text ".Layer_Name" at 577,-858.49 h60
M11 Gerber Information:
  lines w10: -292,-930.17 6308,-930.17 ; -292,-726.83 6310,-726.83 ; -292,-523.5 -292,-1133.5 3713,-1133.5 6310,-1133.5 6310,-523.5 -291.5,-523.5 -291.5,-1133.5 1284,-1133.5 ; 2173,-1133.5 2173,-523.5 ; 3440,-726.83 3440,-523.5 ; 4280,-726.83 4280,-523.5 ; 4902,-1140 4902,-937.17
  text "ALL ARTWORK VIEWED FROM TOP SIDE" at -228.5,-655.67 h60
  text "BOARD #:" at 2248,-655.67 h60
  text ".PRJ_Number" at 2793.5,-655.67 h60
  text "REV:" at 3638,-655.67 h60
  text ".PCB_Rev" at 3929.5,-655.67 h60
  text "SVN REV:" at 4476,-655.67 h60
  text ".VersionControl_RevNumber" at 4982,-655.67 h60
  text "LAYER NAME =" at -228.5,-858.49 h60
  text "PLOT NAME =" at -228.5,-1064.34 h60
  text ".plot_File_Name" at 577,-1064.34 h60
  text "GENERATED    :" at 2250,-1064.34 h60
  text ".Print_Date" at 3119.5,-1064.34 h60
  text ".Print_Time" at 3848.5,-1064.34 h60
  text "TEXAS INSTRUMENTS" at 5113,-1064.34 h60
M12 Stackup:
  lines w7: 6630.47,6546.3 10350.84,6546.3 ; 6630.47,6672.2 10350.84,6672.2 ; 6570.47,5300.52 ccw(c6611.47,5300.52) 6611.47,5259.52 10369.84,5259.52 ccw(c10369.84,5300.52) 10410.84,5300.52 10410.84,6758.46 ccw(c10369.84,6758.46) 10369.84,6799.46 6611.47,6799.46 ccw(c6611.47,6758.46) 6570.47,6758.46 6570.47,5300.52
  text "Layer Stack Up Detail for: Skylake-3.PcbDoc" at 6630.47,6700.93 h48
  text "Layer" at 6630.47,6625.2 h29
  text "Gerber" at 7925.37,6625.2 h29
  text "Copper" at 8821.13,6625.2 h29
  text "Dielectric" at 9764.24,6625.2 h29
  text "Name" at 6630.47,6567.2 h29
  text "Document" at 7925.37,6567.2 h29
  text "Thickness" at 8821.13,6567.2 h29
  text "Material" at 9764.24,6567.2 h29
  text "Top Solder Mask" at 6630.47,6485.06 h41
  text "(.GTS)" at 7925.37,6485.06 h41
  text "Solder Resist" at 9764.24,6485.06 h41
  text "TOP LAYER" at 6630.47,6369.56 h41
  text "(.GTL)" at 7925.37,6369.56 h41
  text "2.8mil" at 8821.13,6369.56 h41
  text "FR-4" at 9764.24,6311.81 h41
  text "GND1#2" at 6630.47,6254.06 h41
  text "(.G1)" at 7925.37,6254.06 h41
  text "2.8mil" at 8821.13,6254.06 h41
  text "FR-4" at 9764.24,6196.32 h41
  text "SIG1#3" at 6630.47,6138.57 h41
  text "(.G2)" at 7925.37,6138.57 h41
  text "1.4mil" at 8821.13,6138.57 h41
  text "FR-4" at 9764.24,6080.82 h41
  text "SIG2#4" at 6630.47,6023.07 h41
  text "(.G3)" at 7925.37,6023.07 h41
  text "1.4mil" at 8821.13,6023.07 h41
  text "FR-4" at 9764.24,5965.33 h41
  text "GND2#5" at 6630.47,5907.58 h41
  text "(.G4)" at 7925.37,5907.58 h41
  text "2.8mil" at 8821.13,5907.58 h41
  text "FR-4" at 9764.24,5849.83 h41
  text "SIG3#6" at 6630.47,5792.08 h41
  text "(.G5)" at 7925.37,5792.08 h41
  text "1.4mil" at 8821.13,5792.08 h41
  text "FR-4" at 9764.24,5734.34 h41
  text "GND3#7" at 6630.47,5676.59 h41
  text "(.G6)" at 7925.37,5676.59 h41
  text "2.8mil" at 8821.13,5676.59 h41
  text "FR-4" at 9764.24,5618.84 h41
  text "BOTTOM LAYER" at 6630.47,5561.09 h41
  text "(.GBL)" at 7925.37,5561.09 h41
  text "2.8mil" at 8821.13,5561.09 h41
  text "Bottom Solder Mask" at 6630.47,5445.6 h41
  text "(.GBS)" at 7925.37,5445.6 h41
  text "Solder Resist" at 9764.24,5445.6 h41
  text ".Layer_Name" at 577,-858.49 h60
M13 Component Bodies Top:
  text ".Layer_Name" at 577,-858.49 h60
M14 Component Bodies Bottom:
  text ".Layer_Name" at 577,-858.49 h60
M15 Courtyards Top:
  text ".Layer_Name" at 577,-858.49 h60
M16 Courtyards Bottom:
  text ".Layer_Name" at 577,-858.49 h60
Drill Drawing:
  circle w1: c6047.12,566 r25
  lines w1: 6022.12,691 6047.12,703.5 6072.12,691 6059.62,716 6072.12,741 6047.12,728.5 6022.12,741 6034.62,716 6022.12,691 ; 6022.12,853.5 6034.62,853.5 6047.12,841 6059.62,853.5 6072.12,853.5 6059.62,866 6072.12,878.5 6059.62,878.5 6047.12,891 6034.62,878.5 6022.12,878.5 6034.62,866 6022.12,853.5 ; 6022.12,1041 6072.12,1041 6047.12,991 6022.12,1041 ; 6022.12,1141 6072.12,1141 6072.12,1191 6022.12,1191 6022.12,1141 ; 6022.12,1303.5 6034.62,1303.5 6034.62,1291 6059.62,1291 6059.62,1303.5 6072.12,1303.5 6072.12,1328.5 6059.62,1328.5 6059.62,1341 6034.62,1341 6034.62,1328.5 6022.12,1328.5 6022.12,1303.5 ; 6022.12,1441 6022.12,1453.5 6034.62,1466 6022.12,1478.5 6022.12,1491 6034.62,1491 6047.12,1478.5 6059.62,1491 6072.12,1491 6072.12,1478.5 6059.62,1466 6072.12,1453.5 6072.12,1441 6059.62,1441 6047.12,1453.5 6034.62,1441 6022.12,1441
  lines w15: 5954,496 9832.97,496 ; 5954,1546 9832.97,1546 ; 6504.88,346 6504.88,1696 ; 7202.69,346 7202.69,1696 ; 8548.29,346 8548.29,1696 ; 9054.17,346 9054.17,1696 ; 5954,346 9832.97,346 9832.97,1696 5954,1696 5954,346
  text "Symbol" at 6044,1591 h72
  text "Hit Count" at 6549.88,1591 h72
  text "Finished Hole Size" at 7247.69,1591 h72
  text "Plated" at 8593.29,1591 h72
  text "Hole Type" at 9099.17,1591 h72
  text "2" at 6549.88,1441 h60
  text "270.00mil (6.858mm)" at 7247.69,1441 h60
  text "PTH" at 8593.29,1441 h60
  text "Round" at 9099.17,1441 h60
  text "4" at 6549.88,1291 h60
  text "125.98mil (3.200mm)" at 7247.69,1291 h60
  text "PTH" at 8593.29,1291 h60
  text "Round" at 9099.17,1291 h60
  text "10" at 6549.88,1141 h60
  text "7.87mil (0.200mm)" at 7247.69,1141 h60
  text "PTH" at 8593.29,1141 h60
  text "Round" at 9099.17,1141 h60
  text "18" at 6549.88,991 h60
  text "38.00mil (0.965mm)" at 7247.69,991 h60
  text "PTH" at 8593.29,991 h60
  text "Round" at 9099.17,991 h60
  text "30" at 6549.88,841 h60
  text "40.00mil (1.016mm)" at 7247.69,841 h60
  text "PTH" at 8593.29,841 h60
  text "Round" at 9099.17,841 h60
  text "46" at 6549.88,691 h60
  text "63.00mil (1.600mm)" at 7247.69,691 h60
  text "PTH" at 8593.29,691 h60
  text "Round" at 9099.17,691 h60
  text "742" at 6549.88,541 h60
  text "10.00mil (0.254mm)" at 7247.69,541 h60
  text "PTH" at 8593.29,541 h60
  text "Round" at 9099.17,541 h60
  text "852 Total" at 6549.88,391 h60
  text ".Layer_Name" at 577,-858.49 h60

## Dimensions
520,2965 to 520,825 on M10 Fab Notes
520,2965 to 3675,2965 on M10 Fab Notes
0,0 to 4000,0 on M2 Board Dimensions
0,0 to 0,4000 on M2 Board Dimensions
